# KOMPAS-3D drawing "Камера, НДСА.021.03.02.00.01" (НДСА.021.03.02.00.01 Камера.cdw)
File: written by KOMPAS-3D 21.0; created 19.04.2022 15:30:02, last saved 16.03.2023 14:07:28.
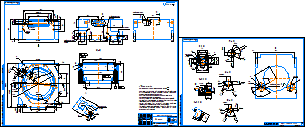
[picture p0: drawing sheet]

Sheet 1: A1, landscape
Sheet 2: A2, landscape

Document properties: Полное имя файла: C:\Users\korychko\Desktop\PLM\НДСА.021.03.02.00.01 Камера.cdw; PLM_CDWXDTO: <item xmlns="http://appius.ru/pdm" xmlns:xs="http://www.w3.org/2001/XMLSchema" xmlns:xsi="http://www.w3.org/2001/XMLSchema-instance" xsi:type="item">  <element xmlns:d2p1="http://v8.1c.ru/8.1/data/enterprise/current-config" xsi:type="d2p1:CatalogRef.aps_Элемен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; Масса: 77.149999; Знак неуказанной шероховатости: 4; Параметр неуказанной шероховатости: Ra 3,2; PDM_DOCXDTO: <item xmlns="http://appius.ru/pdm" xmlns:xs="http://www.w3.org/2001/XMLSchema" xmlns:xsi="http://www.w3.org/2001/XMLSchema-instance" xsi:type="item">  <element xmlns:d2p1="http://v8.1c.ru/8.1/data/enterprise/current-config" xsi:type="d2p1:CatalogRef.aps_Элемен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; PDM_ITEMXDTO: <item xmlns="http://appius.ru/pdm" xmlns:xs="http://www.w3.org/2001/XMLSchema" xmlns:xsi="http://www.w3.org/2001/XMLSchema-instance" xsi:type="item">  <element xmlns:d2p1="http://v8.1c.ru/8.1/data/enterprise/current-config" xsi:type="d2p1:CatalogRef.aps_Элемен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; Форматы листов документа: A2, A1; PDM_DRAWINGXDTO: <item xmlns="http://appius.ru/pdm" xmlns:xs="http://www.w3.org/2001/XMLSchema" xmlns:xsi="http://www.w3.org/2001/XMLSchema-instance" xsi:type="item">  <element xmlns:d2p1="http://v8.1c.ru/8.1/data/enterprise/current-config" xsi:type="d2p1:CatalogRef.aps_Элемен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

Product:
- Part/product: Камера  | designation НДСА.021.03.02.00.01
    Материал: АМг6  ГОСТ 4784-2019 (density 2640 kg/m3)
    Масса: 77.159778
    additional columns: <item xmlns="http://appius.ru/pdm" xmlns:xs="http://www.w3.org/2001/XMLSchema" x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; <item xmlns="http://appius.ru/pdm" xmlns:xs="http://www.w3.org/2001/XMLSchema" x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; <item xmlns="http://appius.ru/pdm" xmlns:xs="http://www.w3.org/2001/XMLSchema" x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
    source file: НДСА.021.03.02.00.01 Камера.cdw

Title block, sheet 1: Наименование: Камера; designation: НДСА.021.03.02.00.01; Материал: АМг6  ГОСТ 4784-2019; Масса: 77,14; sheet number: 1; Количество листов документа: 2; organisation: ЭСТО; Форматы листов документа: A1; stored path: C:\Users\s.pischagina\Desktop\PLM\НДСА.021.03.02.00.01 Камера.cdw; Разработал: Пищагина; Проверил: Белецкий; Утвердил: Виноградов; Разработал, date: 21.04.22
Title block, sheet 2: Масса: 77,16; sheet number: 2; Форматы листов документа: A2

Views: Вид 1, Местный разрез 1, Спереди, Проекционный вид 2, Местный разрез 2, Проекционный вид 4, Вид по стрелке 7, Выносной элемент 9, Выносной элемент 10, Разрез Ж-Ж, Выносной элемент 12, Разрез К-К, Вид по стрелке А, Вид по стрелке Б, Выносной элемент В, Выносной элемент, Выносной элемент Г, Выносной элемент Д, Разрез И-И, Выносной элемент Е
Referenced files in C:\Users\korychko\Desktop\PLM\: НДСА.021.03.02.00.01 Камера.m3d
Referenced files in C:\Users\s.pischagina\Desktop\PLM\: НДСА.021.03.02.00.01 Камера.m3d
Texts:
  Ra1.6
  Ra 1,6
  Ra 3,2
  Ra 3,2 ( )
  Корячко
  НДСА.021.03.02.00.01 Камера
Dimensions and other numbers on the sheet: 300±0,05; 43,25; 38,5; 236; 358; 20; 48; 10; 2 отв.; -7Н; 8; 6отв; 232; 480±0,3; 12; 15; 140; 2; 3отв; 187,5; 375±0,3; 38; 143,5; 50; 128; 281±0,1; 521±0,1; 408; 436; 5; 2отв; 37 30'; 229; 31; 9,7; 1.6; 32,8; 4; 6; 1; 2 фаски; 25; 15,5; 16; 4отв М3-7Нх10-14; 2места; 440; 200; 55; 3отв М6-7Нх10-15; 106±1; 120; 3±0,05; 2,5; 0,8; 0,25; 4,65±0,05; 0,4; 4,5; 12,65; 24; 27; 18; 70; 1:2,49; 77,14; 21.04.22; 06.03.2023; 15.03.2023; 1249; 1295; 77,16

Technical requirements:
  *Размеры для справок
  Неуказанные предельные отклонения H12, h12,    IT12 2 .
  Покрытие Ан. Окс. 50 мкм, поверхности Н и резьбовые отверстия
  не обрабатываются. Удаление покрытия возможно выполнением
  постобработки или формированием маски.
  Все размеры указаны после формирования покрытия Ан.Окс.
  Материал-заменитель алюминий 7021.
  На поверхностях не допускается наличие царапин и дефектов.
  Место выхода инструмента для формирования канавок, может
  быть установлено в произвольном положении.
  После завершения всех процессов обработки произвести
  очистку. После очистки голыми руками не прикасаться.
  Поставка детали осуществляется в упаковке. Упаковка должна
  обеспечивать сохранность изделия от царапин и других
  механических повреждений.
